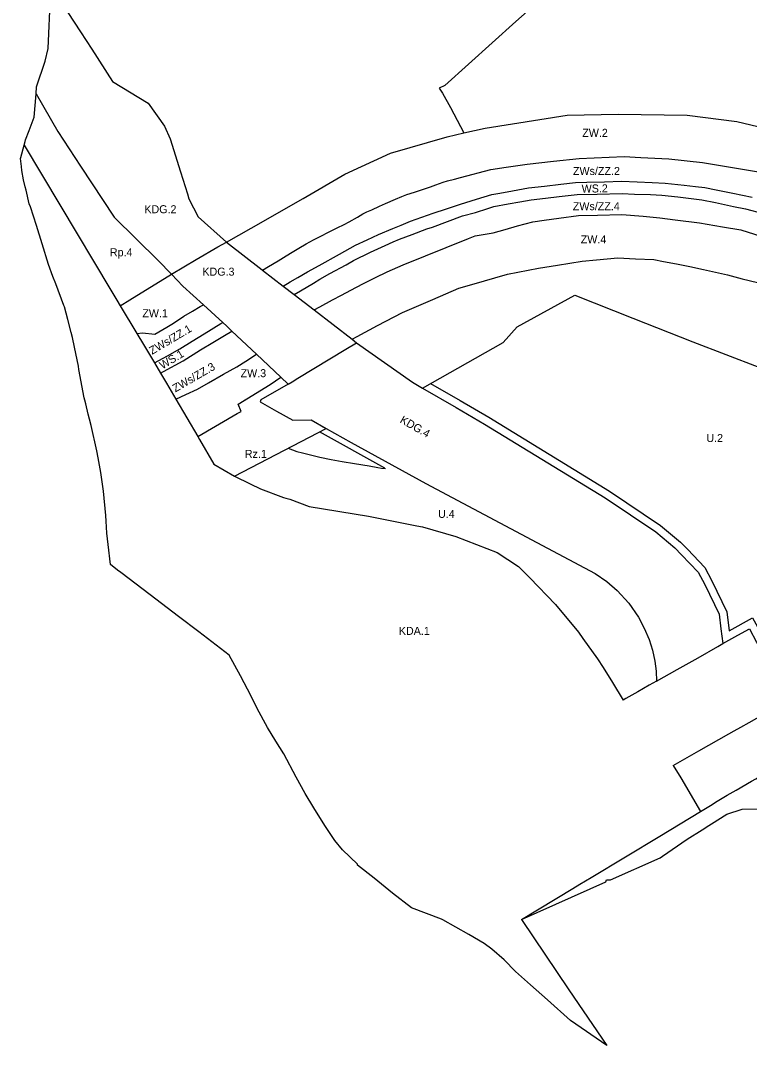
# Model space of a CAD drawing. Extents: x 7414808 to 7417449, y 5544732 to 5546764.
# Drawn here: x 7414942 to 7415397, y 5544732 to 5545373 of the extents above; entities that cross this region are included whole.
import ezdxf

# ---------------------------------------------------------------- set-up
doc = ezdxf.new("R2010")
doc.units = 0
for name, color, linetype in [('LIN_Linie Rozgraniczajace', 7, 'Continuous'), ('LIN_nieprzekraczale linie zabudowy', 7, 'Continuous'), ('TXT_Oznaczenia Przeznaczenia', 7, 'Continuous')]:
    doc.layers.add(name, color=color, linetype=linetype)

msp = doc.modelspace()

# ---------------------------------------------------------------- linework, layer by layer
at = {"layer": 'LIN_Linie Rozgraniczajace'}
for p, q in [((7415025.29, 5545158.94), (7415029.05, 5545152.67)), ((7415038.71, 5545136.29), (7415052.33, 5545113.02)), ((7415075.32, 5545088.28), (7415132.63, 5545118.05))]:
    msp.add_line(p, q, dxfattribs=at)
for points in [[(7415312.43, 5545424.43), (7415288.68, 5545405.72), (7415251.03, 5545372.38)], [(7414951.29, 5545327.19), (7414951.66, 5545331.58), (7414956.97, 5545347.63), (7414958.95, 5545355.47), (7414960.34, 5545388.52)], [(7414960.34, 5545388.52), (7414967.23, 5545384.1), (7414979.04, 5545365.94), (7414986.08, 5545355.13), (7414999.04, 5545334.96), (7415021.31, 5545321.41), (7415031.52, 5545306.93), (7415035.18, 5545299.08), (7415041.54, 5545278.35), (7415045.93, 5545264.7), (7415046.82, 5545261.63), (7415052.56, 5545250.21), (7415070.23, 5545234.46)], [(7415251.03, 5545372.38), (7415206.72, 5545332.33), (7415203.11, 5545330.64), (7415205.29, 5545327.66), (7415210.19, 5545318.68), (7415218.73, 5545302.75)], [(7414943.82, 5545294.99), (7414944.47, 5545297.39), (7414944.72, 5545298.34), (7414946.94, 5545304.25), (7414950.04, 5545312.49), (7414951.29, 5545327.19)], [(7414951.29, 5545327.19), (7414964.94, 5545303.53), (7414979.16, 5545281.86), (7415000.06, 5545250), (7415027.65, 5545223.05), (7415036, 5545214.35)], [(7415218.73, 5545302.75), (7415231.9, 5545305.73), (7415283.13, 5545313.83), (7415315.06, 5545314.38), (7415358.1, 5545313.84), (7415389.19, 5545309.83), (7415415.45, 5545303.53), (7415455.5, 5545290.5), (7415508.79, 5545266.77), (7415528.75, 5545255.18)], [(7415070.23, 5545234.46), (7415085.65, 5545243.21), (7415118.3, 5545261.64), (7415144.31, 5545276.91), (7415172.84, 5545290.02), (7415208.23, 5545300.38), (7415218.73, 5545302.75)], [(7415254.6, 5544811.06), (7415284.19, 5544767.13), (7415308, 5544732.39), (7415285.35, 5544747.98), (7415270.91, 5544760.91), (7415260.25, 5544770.3), (7415251.01, 5544778.74), (7415243.89, 5544785.84), (7415236.1, 5544792.59), (7415231.31, 5544796.07), (7415221.78, 5544801.85), (7415205.49, 5544810.85), (7415204.76, 5544811.25), (7415185.87, 5544818.44), (7415174.04, 5544827.64), (7415162.58, 5544837.04), (7415152.25, 5544845.04), (7415152.27, 5544845.82), (7415142.86, 5544854.78), (7415138.05, 5544860.58), (7415131.73, 5544869.91), (7415124.98, 5544880.94), (7415119.55, 5544889.84), (7415113.75, 5544900.05), (7415106.07, 5544914.72), (7415101.11, 5544922.69), (7415095.99, 5544931.09), (7415089.42, 5544943.01), (7415085.62, 5544950.8), (7415079, 5544963.42), (7415072.07, 5544976.27), (7415052.98, 5544990.84), (7415040.27, 5545000.55), (7415022.69, 5545013.97), (7415004.3, 5545028), (7415002.28, 5545029.54), (7414997.82, 5545032.94), (7414996.4, 5545045.46), (7414995.58, 5545052.63), (7414995.14, 5545060.04), (7414994.81, 5545063.66), (7414993.44, 5545078.86), (7414991.79, 5545090.51), (7414990.05, 5545099.6), (7414989.26, 5545103.96), (7414985.68, 5545119.88), (7414984.68, 5545123.9), (7414983.9, 5545127.02), (7414982.35, 5545133.31), (7414981.77, 5545135.62), (7414981.39, 5545137.19), (7414978.02, 5545154.95), (7414977.81, 5545156.9), (7414975.34, 5545168.8), (7414974.11, 5545174.89), (7414973.27, 5545178.02), (7414971.05, 5545186.21), (7414969.04, 5545193.98), (7414968.68, 5545194.93), (7414963.58, 5545208.51), (7414961.67, 5545213.05), (7414959.14, 5545220.53), (7414955.14, 5545233.33), (7414951.66, 5545244.95), (7414947.86, 5545256.51), (7414946.95, 5545258.36), (7414945.07, 5545266.92), (7414944.52, 5545269.08), (7414943.4, 5545273.51), (7414942.34, 5545279.32), (7414942.09, 5545281.82), (7414941.56, 5545286.75), (7414941.77, 5545287.29), (7414943.82, 5545294.99)], [(7414943.82, 5545294.99), (7414966.06, 5545257.85), (7414998.07, 5545204.41), (7414999.9, 5545201.35), (7415001.8, 5545198.17), (7415003.88, 5545194.71)], [(7415092.78, 5545217.05), (7415096.5, 5545219.24), (7415102.51, 5545222.81), (7415107.56, 5545225.88), (7415111.34, 5545228.13), (7415115.54, 5545230.65), (7415120, 5545233.31), (7415124.77, 5545235.87), (7415129.63, 5545238.45), (7415133.63, 5545240.54), (7415139.4, 5545243.31), (7415143.8, 5545245.46), (7415146.99, 5545247.25), (7415152.13, 5545250.17), (7415155.6, 5545252.17), (7415158.09, 5545253.37), (7415161.16, 5545254.76), (7415165.89, 5545256.93), (7415169.59, 5545258.61), (7415175.92, 5545261.36), (7415179.85, 5545263.06), (7415182.91, 5545264.17), (7415187.71, 5545265.71), (7415192.73, 5545267.36), (7415197.84, 5545269.01), (7415201.13, 5545270.19), (7415205.76, 5545271.96), (7415208.51, 5545272.81), (7415212.76, 5545273.83), (7415216.55, 5545274.81), (7415235.4, 5545279.78), (7415245.05, 5545281.23), (7415258.14, 5545283.14), (7415274.69, 5545285.03), (7415290.74, 5545286.8), (7415318.8, 5545288.07), (7415329.32, 5545287.45), (7415346.68, 5545286.5), (7415367.87, 5545284.27), (7415403.95, 5545278.26)], [(7415105.79, 5545207.01), (7415110.01, 5545209.67), (7415114.91, 5545212.41), (7415120.91, 5545215.81), (7415128.12, 5545219.9), (7415141.02, 5545227.03), (7415150.87, 5545232.53), (7415158.18, 5545235.94), (7415165.29, 5545239.17), (7415174.31, 5545242.96), (7415179.39, 5545245.02), (7415185.3, 5545247.54), (7415199.5, 5545252.49), (7415207.72, 5545255.27), (7415216.52, 5545258.22), (7415226.49, 5545261.29), (7415236.11, 5545264.25), (7415241.14, 5545265.11), (7415249.05, 5545266.58), (7415259.14, 5545268.38), (7415269.1, 5545269.47), (7415279.35, 5545270.66), (7415288.47, 5545271.67), (7415295.4, 5545271.91), (7415306.55, 5545272.19), (7415317.18, 5545272.57), (7415326.96, 5545272.09), (7415336.3, 5545271.67), (7415344.35, 5545271.33), (7415356.23, 5545269.98), (7415363.41, 5545269.24), (7415369.14, 5545268.61), (7415376.29, 5545267.17), (7415386.71, 5545265.04), (7415398.74, 5545262.56)], [(7415112.68, 5545201.69), (7415116.47, 5545203.98), (7415124.57, 5545208.9), (7415128.58, 5545211.32), (7415134.96, 5545214.85), (7415145, 5545220.38), (7415149.67, 5545222.95), (7415160.28, 5545228.15), (7415169.54, 5545232.42), (7415174.36, 5545234.56), (7415178.47, 5545236.23), (7415186.41, 5545239.27), (7415195.48, 5545242.79), (7415198.99, 5545243.89), (7415217.71, 5545250.96), (7415225.88, 5545253), (7415233.68, 5545255.49), (7415237.42, 5545256.78), (7415246.27, 5545258.32), (7415253.62, 5545259.65), (7415260.73, 5545260.89), (7415269.64, 5545261.91), (7415278.13, 5545262.89), (7415289.37, 5545264.26), (7415301.98, 5545264.49), (7415317.66, 5545264.82), (7415325.37, 5545264.5), (7415335.28, 5545264.14), (7415342.42, 5545263.85), (7415352.31, 5545262.7), (7415367.45, 5545260.93), (7415376, 5545259.15), (7415387.24, 5545256.78), (7415394.59, 5545255.24), (7415405.8, 5545252.34)], [(7415125.07, 5545192.13), (7415128.66, 5545194.07), (7415136.62, 5545198.39), (7415142.11, 5545201.37), (7415147.95, 5545204.46), (7415155.52, 5545208.48), (7415163.42, 5545212.36), (7415170.72, 5545215.9), (7415180.72, 5545220.37), (7415221.58, 5545236.81), (7415225.79, 5545238.41), (7415236.87, 5545240.19), (7415244.44, 5545242.46), (7415252.09, 5545244.63), (7415261.79, 5545247.25), (7415268.75, 5545248.2), (7415278, 5545249.43), (7415290.19, 5545251.17), (7415302.24, 5545251.39), (7415317.29, 5545251.74), (7415330.61, 5545250.63), (7415341.19, 5545249.68), (7415350.68, 5545248.48), (7415365.97, 5545246.46), (7415380.38, 5545244.06), (7415391.71, 5545242.23), (7415404.26, 5545238.29)], [(7415036, 5545214.35), (7415051.31, 5545223.72), (7415064.95, 5545231.46), (7415070.23, 5545234.46)], [(7415070.23, 5545234.46), (7415092.62, 5545217.17), (7415092.78, 5545217.05)], [(7415148.83, 5545173.79), (7415152.05, 5545175.49), (7415164.77, 5545182.3), (7415180.24, 5545190.52), (7415199.22, 5545198.72), (7415215.43, 5545205.6), (7415223.67, 5545208.03), (7415245.98, 5545214.46), (7415265.33, 5545218.25), (7415277.15, 5545220.06), (7415292.56, 5545222.57), (7415301.64, 5545223.38), (7415314.87, 5545224.63), (7415325.88, 5545224.06), (7415337.41, 5545223.55), (7415343.41, 5545222.39), (7415351.5, 5545220.83), (7415359.94, 5545219.28), (7415368.48, 5545217.36), (7415383.51, 5545213.97), (7415392.67, 5545211.59), (7415407.31, 5545207.92)], [(7415092.78, 5545217.05), (7415105.79, 5545207.01)], [(7415003.88, 5545194.71), (7415009.98, 5545198.44), (7415036, 5545214.35)], [(7415036, 5545214.35), (7415043.07, 5545206.93), (7415055.85, 5545195.33)], [(7415105.79, 5545207.01), (7415112.68, 5545201.69)], [(7415014.2, 5545177.47), (7415017.9, 5545177.74), (7415025.52, 5545177.03), (7415033, 5545181.42), (7415037.14, 5545183.86), (7415043.67, 5545188.13), (7415049.09, 5545191.39), (7415053.92, 5545194.19), (7415055.85, 5545195.33)], [(7415055.85, 5545195.33), (7415067.98, 5545184.27)], [(7415112.68, 5545201.69), (7415125.07, 5545192.13)], [(7415192.85, 5545143.26), (7415243.15, 5545171.84), (7415251.87, 5545181.6), (7415287.99, 5545201.37), (7415324.15, 5545186.94), (7415361.75, 5545172.1), (7415402.89, 5545156.35), (7415451.13, 5545137.38), (7415471.07, 5545129.37), (7415474.52, 5545127.99)], [(7415003.88, 5545194.71), (7415014.2, 5545177.47), (7415018.37, 5545170.5), (7415025.29, 5545158.94)], [(7415125.07, 5545192.13), (7415148.83, 5545173.79)], [(7415025.29, 5545158.94), (7415033.38, 5545163.45), (7415041.08, 5545167.84), (7415048.91, 5545172.55), (7415056.28, 5545177.09), (7415066.69, 5545183.52), (7415067.98, 5545184.27)], [(7415067.98, 5545184.27), (7415070.58, 5545181.96), (7415073.71, 5545178.88)], [(7415029.05, 5545152.67), (7415030.92, 5545153.69), (7415043.15, 5545160.3), (7415054.03, 5545167.09), (7415061.71, 5545171.76), (7415069.11, 5545176.14), (7415073.71, 5545178.88)], [(7415073.71, 5545178.88), (7415089.09, 5545164.41)], [(7415108.91, 5545145.76), (7415111.24, 5545147.1), (7415114.87, 5545149.5), (7415144.94, 5545167.63), (7415151.57, 5545171.62)], [(7415148.83, 5545173.79), (7415151.57, 5545171.62)], [(7415151.57, 5545171.62), (7415186.59, 5545146.86), (7415192.85, 5545143.26)], [(7415038.71, 5545136.29), (7415044.99, 5545139.27), (7415052.12, 5545142.61), (7415059.09, 5545146.62), (7415068.37, 5545151.87), (7415076.74, 5545156.45), (7415082.32, 5545160.1), (7415089.09, 5545164.41)], [(7415089.09, 5545164.41), (7415104.21, 5545150.18)], [(7415029.05, 5545152.67), (7415032.86, 5545146.3), (7415038.71, 5545136.29)], [(7415052.33, 5545113.02), (7415077.01, 5545127.29), (7415079.4, 5545128.67), (7415077.56, 5545133.22), (7415097.51, 5545145.41), (7415104.21, 5545150.18)], [(7415108.91, 5545145.76), (7415091.72, 5545135.81), (7415091.39, 5545134.56), (7415101.49, 5545128.88), (7415111.67, 5545123.16), (7415123.25, 5545123.37), (7415132.63, 5545118.05), (7415148.2, 5545109.24), (7415194.94, 5545083.69), (7415300.69, 5545027.35), (7415307.9, 5545022.41), (7415314.53, 5545016.71), (7415321.74, 5545008.8), (7415327.83, 5545000), (7415331.43, 5544993.26), (7415334.37, 5544986.21), (7415336.48, 5544979.48), (7415337.98, 5544972.58), (7415338.81, 5544966.37), (7415339.14, 5544960.11), (7415334.52, 5544957.5), (7415327.38, 5544953.47), (7415319.92, 5544949.24), (7415318.23, 5544948.28)], [(7415104.21, 5545150.18), (7415108.91, 5545145.76)], [(7415192.85, 5545143.26), (7415213.88, 5545131.16), (7415231.59, 5545120.77), (7415306.96, 5545074.67), (7415338.53, 5545053.42), (7415350.59, 5545043.35), (7415354.69, 5545039.05), (7415365.06, 5545028.17), (7415369.18, 5545020.59), (7415378.22, 5545002.03), (7415379.3, 5544992.76), (7415380.57, 5544983.54)], [(7415052.33, 5545113.02), (7415053.38, 5545111.22), (7415062.44, 5545095.74), (7415075.32, 5545088.28)], [(7415075.32, 5545088.28), (7415085.05, 5545083.47), (7415091.57, 5545080.25), (7415105.89, 5545074.82), (7415107.45, 5545074.38), (7415109.82, 5545073.73), (7415121.89, 5545069.3), (7415159.02, 5545063.31), (7415189.26, 5545057.25), (7415192.84, 5545056.53), (7415213.56, 5545050.57), (7415239.48, 5545040.5), (7415252.86, 5545031.8), (7415259.83, 5545024.64), (7415276, 5545008.06), (7415290.23, 5544990.75), (7415293.05, 5544986.81), (7415302.16, 5544974.05), (7415305.64, 5544968.53), (7415311.53, 5544959.23), (7415318.23, 5544948.28)], [(7415396.9, 5544934.26), (7415422.13, 5544948.54), (7415419.31, 5544953.25), (7415515.79, 5544996.52), (7415549.22, 5545010.98), (7415612.74, 5545035.49)], [(7415339.14, 5544960.11), (7415351.96, 5544967.37), (7415365.01, 5544974.74), (7415377.38, 5544981.74), (7415380.57, 5544983.54), (7415389.95, 5544988.84), (7415397.06, 5544992.86), (7415401.63, 5544984.52), (7415406.06, 5544976.46), (7415407.65, 5544973.56), (7415413.1, 5544963.62), (7415419.31, 5544953.25)], [(7415254.6, 5544811.06), (7415307.29, 5544834.58), (7415307.72, 5544835.91), (7415310.37, 5544835.96), (7415341.31, 5544849.77), (7415342.78, 5544850.78), (7415358.22, 5544861.35), (7415367.57, 5544867.18), (7415371.76, 5544869.79), (7415373.42, 5544870.83), (7415383.07, 5544877), (7415392.48, 5544880.16), (7415416.88, 5544880.57), (7415432.92, 5544884.91), (7415459.21, 5544895.37), (7415475.98, 5544907.34), (7415501.33, 5544935.46), (7415521.54, 5544954.89)], [(7415366.55, 5544878.69), (7415372.72, 5544882.43), (7415377, 5544885.02), (7415383.2, 5544888.77), (7415388.88, 5544892.06), (7415398.49, 5544897.62), (7415401.04, 5544899.1), (7415410.17, 5544904.39), (7415413.81, 5544906.5), (7415419.85, 5544909.32), (7415459.07, 5544927.72), (7415459.92, 5544928.09), (7415478.35, 5544936.32), (7415495.36, 5544943.9), (7415503.89, 5544947.71), (7415508.17, 5544949.45), (7415521.54, 5544954.89)], [(7415349.52, 5544907.47), (7415365.41, 5544916.46), (7415384.27, 5544927.13), (7415387.55, 5544928.98), (7415391.79, 5544931.37), (7415396.9, 5544934.26)], [(7415349.52, 5544907.47), (7415354.14, 5544899.75), (7415366.55, 5544878.69)], [(7415254.6, 5544811.06), (7415286.77, 5544830.49), (7415291.15, 5544833.14), (7415298.25, 5544837.43), (7415341.07, 5544863.26), (7415366.55, 5544878.69)]]:
    msp.add_lwpolyline(points, dxfattribs=at)
at = {"layer": 'LIN_nieprzekraczale linie zabudowy'}
for points in [[(7415197.89, 5545146.13), (7415216.39, 5545135.48), (7415234.16, 5545125.06), (7415309.66, 5545078.88), (7415341.54, 5545057.42), (7415354.01, 5545047.01), (7415358.31, 5545042.5), (7415369.14, 5545031.14), (7415373.63, 5545022.88), (7415383.09, 5545003.45), (7415384.48, 5544991.49), (7415399.01, 5544999.71), (7415421.32, 5544959.63)], [(7415081.54, 5545135.52), (7415081.42, 5545135.58)], [(7415130.49, 5545118.87), (7415130.4, 5545118.92)], [(7415169.2, 5545093.21), (7415128.4, 5545115.85)], [(7415108.84, 5545105.69), (7415114.25, 5545103.7), (7415117.71, 5545102.87), (7415128.59, 5545100.11), (7415135.73, 5545098.55), (7415142.54, 5545097.35), (7415150.33, 5545096.09), (7415159.51, 5545094.75), (7415164.86, 5545093.72), (7415167.24, 5545093.31), (7415169.6, 5545092.97)]]:
    msp.add_lwpolyline(points, dxfattribs=at)

# ---------------------------------------------------------------- texts
at = {"layer": 'TXT_Oznaczenia Przeznaczenia'}
for s, p in [('ZW.2', (7415292.64, 5545300.28)), ('ZWs/ZZ.2', (7415286.83, 5545276.44)), ('ZWs/ZZ.4', (7415286.74, 5545254.44)), ('KDG.2', (7415018.97, 5545252.53)), ('ZW.4', (7415291.68, 5545233.7)), ('Rp.4', (7414997.41, 5545225.64)), ('KDG.3', (7415055.24, 5545213.52)), ('ZW.1', (7415017.69, 5545187.51)), ('ZW.3', (7415079.11, 5545150.07)), ('U.2', (7415370.19, 5545109.54)), ('Rz.1', (7415081.75, 5545099.64)), ('U.4', (7415202.53, 5545062.14)), ('KDA.1', (7415178.01, 5544989.02))]:
    msp.add_text(s, height=5, dxfattribs=at).set_placement(p)
for s, rotation, p in [('WS.2', 0.65193, (7415292.27, 5545265.41)), ('ZWs/ZZ.1', 30.66303, (7415023.84, 5545164.01)), ('WS.1', 31.06294, (7415030.25, 5545154.87)), ('ZWs/ZZ.3', 30.10542, (7415038.35, 5545140.49)), ('KDG.4', 330.25896, (7415178.25, 5545121.98))]:
    msp.add_text(s, height=5, rotation=rotation, dxfattribs=at).set_placement(p)

doc.saveas('drawing.dxf')
